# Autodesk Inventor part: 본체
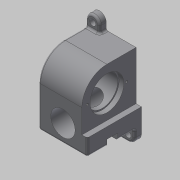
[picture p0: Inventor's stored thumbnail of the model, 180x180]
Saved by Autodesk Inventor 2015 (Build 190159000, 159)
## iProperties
Created: 2019-06
Part Number: 본체
Material: 일반
Document SubType Name: Modeling
Designer: mduedu
Density: 1 g/cm^3
Appearance: 기본값
Author: mduedu
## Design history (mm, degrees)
sketch "스케치1"
  geometry: L1 (37, 0)-(37, -43); L2 (37, -43)-(-60, -43); L3 (-60, -43)-(-60, 37); L4 (-60, 37)-(0, 37); A1 r 37 centre (0, 0) between (37, 0) and (0, 37); 1 further point
  constraints: 8 end point, 2 point on circle, 2 tangent, 1 centre point, 1 coincident, 1 horizontal, 1 parallel, 1 perpendicular, 1 vertical
  dimensions: "d0" = 37 radius of A1; "d2" = 80 distance of L2.end L3.end; "d3" = 97 distance of L1.end L2.end
extrude "돌출1" new body sketch "스케치1" stored distance "d4" = 72; taper "d5" = 0 deg
sketch "스케치2"
  geometry: L1 (72, 25)-(64, 25); L2 (64, 25)-(64, 97); L3 (64, 97)-(72, 97); L4 (72, 97)-(72, 25); L5 (72, 97)-(0, 97) reference; L6 (72, 60)-(72, 0) reference; 1 further point
  constraints: 8 end point, 2 collinear, 2 parallel, 1 horizontal, 1 perpendicular
  dimensions: "d6" = 72 distance between parallel lines of L1 L3; "d8" = 8 distance of L1.start L1.end
extrude "돌출2" cut sketch "스케치2" stored distance "d9" = 72; taper "d10" = 0 deg
sketch "스케치3"
  geometry: L1 (-36, -60)-(-36, 37) reference; L2 (-36, 37)-(28, 37) reference; L3 (28, 37)-(28, -35) reference; L4 (28, -35)-(36, -35) reference; L5 (36, -35)-(36, -60) reference; L6 (36, -60)-(-36, -60) reference; L7 (-36, 0)-(-19, 0); L8 (-19, 0)-(-19, 17.5); L9 (-19, 17.5)-(-36, 17.5); L10 (-36, 17.5)-(-36, 0); L11 (-19, 0)-(21, 0); L12 (21, 0)-(21, 23); L13 (21, 23)-(-19, 23); L14 (-19, 23)-(-19, 0); L15 (21, 0)-(28, 0); L16 (28, 0)-(28, 25); L17 (28, 25)-(21, 25); L18 (21, 25)-(21, 0); 1 further point
  constraints: 24 end point, 6 parallel, 3 horizontal, 3 perpendicular, 2 point on line, 1 horizontal alignment
  dimensions: "d11" = 7 distance of L16.end L17.end; "d13" = 47 distance between parallel lines of L3 L8; "d14" = 50 diameter of L17 L15; "d15" = 46 diameter of L13 L11; "d16" = 35 diameter of L9 L7
revolve "회전1" sketch "스케치3" stored, may be unused: angle "d17" = 90 deg
sketch "스케치4"
  geometry: C1 r 28 at (0, 0); 1 further point
  constraints: 1 centre point, 1 coincident
  dimensions: "d18" = 56 diameter of C1
extrude "돌출3" cut sketch "스케치4" distance "d19" = 2; taper "d20" = 0 deg
fillet "모깎기1" dims "d21" = 3
sketch "스케치5"
  geometry: C1 r 18 at (36, 26); 1 further point
  constraints: 1 centre point, 1 vertical alignment
  dimensions: "d22" = 36 diameter of C1; "d23" = 34 distance of C1.centre point (36, 60)
extrude "돌출4" cut sketch "스케치5" stored distance "d24" = 2; taper "d25" = 0 deg
sketch "스케치6"
  geometry: L1 (-37, -60)-(43, -60) reference; L2 (-8, -60)-(8, -60); L3 (8, -60)-(8, -51); L4 (8, -51)-(-8, -51); L5 (-8, -51)-(-8, -60); 2 further points
  constraints: 8 end point, 2 parallel, 1 horizontal, 1 midpoint, 1 perpendicular, 1 point on line, 1 vertical alignment
  dimensions: "d26" = 16 distance between parallel lines of L3 L5; "d28" = 9 distance between parallel lines of L1 L4
extrude "돌출5" cut sketch "스케치6" stored distance "d29" = 2; taper "d30" = 0 deg
sketch "스케치7"
  geometry: L1 (-10, -60)-(10, -60); L2 (10, -60)-(10, -48.967); L3 (10, -48.967)-(-10, -48.967); L4 (-10, -48.967)-(-10, -60); L5 (36, -60)-(-36, -60) reference; 3 further points
  constraints: 8 end point, 2 parallel, 1 collinear, 1 horizontal, 1 midpoint, 1 perpendicular, 1 vertical alignment, 2 other
  dimensions: "d31" = 20 distance of L2.end L3.end
extrude "돌출6" cut sketch "스케치7" stored distance "d33" = 2; taper "d34" = 0 deg
sketch "스케치8"
  geometry: L1 (0, 25)-(8, 25) reference; L2 (8, 25)-(8, 60) reference; L3 (72, 60)-(8, 60) reference; L4 (72, 0)-(72, 60) reference; L5 (72, 0)-(0, 0) reference; L6 (0, 25)-(0, 0) reference; L7 (72, 0)-(0, 0); L8 (0, 0)-(0, -20); L9 (0, -20)-(72, -20); L10 (72, -20)-(72, 0); C1 r 18 at (36, 26) reference; 1 further point
  constraints: 8 end point, 2 parallel, 1 horizontal, 1 perpendicular, 1 point on line
  dimensions: "d35" = 20 distance of L7.end L8.end
extrude "돌출7" join sketch "스케치8" distance "d37" = 10; taper "d38" = 0 deg
sketch "스케치9"
  geometry: L1 (0, -37)-(0, 0) reference; L2 (0, 0)-(64, 0) reference; L3 (64, -37)-(64, 0) reference; L4 (44, 0)-(64, 0); L5 (64, 0)-(64, 20); L6 (64, 20)-(44, 20); L7 (44, 20)-(44, 0); 1 further point
  constraints: 9 end point, 2 perpendicular, 1 horizontal, 1 parallel
  dimensions: "d39" = 20 distance of L2.end L5.end; "d51" = 20 distance of L5.end L6.end
extrude "돌출8" join sketch "스케치9" distance "d41" = 10; taper "d42" = 0 deg
fillet "모깎기2" dims "d43" = 10
sketch "스케치10"
  geometry: L1 (-62, -20)-(-10, -20) reference; L2 (0, -10)-(0, 0) reference; L3 (-72, 0)-(0, 0) reference; L4 (-72, 0)-(-72, -10) reference; C1 r 4.5 at (-62, -10); C2 r 4.5 at (-10, -10); A1 r 10 centre (-62, -10) between (-72, -10) and (-62, -20) reference; A2 r 10 centre (-10, -10) between (-10, -20) and (0, -10) reference; 1 further point
  constraints: 2 centre point, 2 coincident, 1 equal radius
  dimensions: "d44" = 9 diameter of C1
extrude "돌출9" cut sketch "스케치10" stored distance "d45" = 10; taper "d46" = 0 deg
sketch "스케치11"
  geometry: L1 (-64, 10)-(-64, 0) reference; L2 (-44, 0)-(-64, 0) reference; L3 (-44, 0)-(-44, 10) reference; C1 r 4.5 at (-54, 10); A1 r 10 centre (-54, 10) between (-44, 10) and (-64, 10) reference; 1 further point
  constraints: 1 centre point, 1 coincident
  dimensions: "d47" = 9 diameter of C1
extrude "돌출10" cut sketch "스케치11" stored distance "d48" = 10; taper "d49" = 0 deg
fillet "모깎기4" dims "d52" = 3
fillet "모깎기5" dims "d53" = 3
fillet "모깎기6" dims "d54" = 3
fillet "모깎기7" dims "d55" = 3
sketch "스케치12" dims "d56" = 58
  geometry: 3 further points
  constraints: 2 horizontal alignment, 1 coincident, 2 other
hole "구멍1" sketch "스케치12" at (66, 35) diameter "d57" = 3.242; stored, may be unused: countersink angle "d61" = 90 deg, drill point angle "d63" = 118 deg; dims "d58" = 10, "d59" = 4, "d60" = 2, "d62" = 12
sketch "스케치13" dims "d67" = 44
  geometry: 3 further points
  constraints: 2 vertical alignment, 1 coincident, 2 other
hole "구멍2" sketch "스케치13" at (0, 22) diameter "d68" = 3.242; stored, may be unused: countersink angle "d72" = 90 deg, drill point angle "d74" = 118 deg; dims "d69" = 10, "d70" = 4, "d71" = 2, "d73" = 12
sketch "스케치14"
  geometry: 3 further points
  constraints: 2 horizontal alignment
  dimensions: "d78" = 25 distance of point (11, 8) point (36, 8); "d79" = 25 distance of point (61, 8) point (36, 8)
hole "구멍3" sketch "스케치14" at (11, 8), (61, 8) diameter "d80" = 3.242; stored, may be unused: countersink angle "d84" = 90 deg, drill point angle "d86" = 118 deg; dims "d81" = 8, "d82" = 4, "d83" = 2, "d85" = 10
node "솔리드1"
pattern_circular "원형 패턴1" dims angle "d65" = 360 deg
pattern_circular "원형 패턴2" dims angle "d76" = 360 deg
node "투영된 루프1"
node "투영된 루프2"
node "투영된 루프3"
node "절단 모서리 투영1"
